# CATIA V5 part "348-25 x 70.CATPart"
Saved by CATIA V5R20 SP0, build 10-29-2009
Part number: 348-25 x 70
Definition: NONE
Nomenclature: 348-25 x 70
Source: Unknown
Description: 348-25 x 70
Bounding box of the stored display mesh (mm): x 0 to 70, y -18 to 18, z -18 to 18
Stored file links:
  C:\Users\Utente\Desktop\IO LAVORO\3D X SITO CF\X SITO\3D files 348\348-25 x 70.CATPart
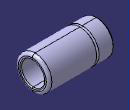
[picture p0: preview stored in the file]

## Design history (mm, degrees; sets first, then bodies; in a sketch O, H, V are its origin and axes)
Body1 "348-25 x 70" (main body)
  Solid1: solid without history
